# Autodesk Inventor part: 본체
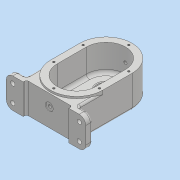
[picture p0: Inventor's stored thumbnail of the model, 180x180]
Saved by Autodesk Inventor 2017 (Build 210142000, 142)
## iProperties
Part Number: 본체
Material: 일반
Document SubType Name: Modeling
Designer: MRC
Density: 1 g/cm^3
Appearance: 기본값
Author: MRC
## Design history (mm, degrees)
sketch "스케치1"
  geometry: L1 (0, 0)-(0, -45); L2 (-40, 0)-(-40, -45); L3 (40, -45)-(40, 0); A1 r 40 centre (0, 0) between (40, 0) and (-40, 0); A2 r 40 centre (0, -45) between (-40, -45) and (40, -45); 1 further point
  constraints: 8 end point, 4 point on circle, 4 tangent, 2 centre point, 1 midpoint, 1 parallel, 1 vertical
  dimensions: "d0" = 45 distance of L1.start L1.end; "d1" = 80 diameter of A2
extrude "돌출1" new body sketch "스케치1" distance "d2" = 21; taper "d4" = 0 deg; dims "d3" = 28, "d5" = 0
sketch "스케치2"
  geometry: L1 (0, 0)-(0, -45); L2 (-30, 0)-(-30, -45); L3 (30, -45)-(30, 0); A1 r 40 centre (0, -45) between (-40, -45) and (40, -45) reference; A2 r 40 centre (0, 0) between (40, 0) and (-40, 0) reference; A3 r 30 centre (0, 0) between (30, 0) and (-30, 0); A4 r 30 centre (0, -45) between (-30, -45) and (30, -45); 1 further point
  constraints: 8 end point, 4 point on circle, 4 tangent, 2 centre point, 1 midpoint, 1 parallel, 1 vertical
  dimensions: "d6" = 30 radius of A3
extrude "돌출2" cut sketch "스케치2" distance "d7" = 41; taper "d8" = 0 deg
sketch "스케치3"
  geometry: L1 (0, 0)-(0, -45); L2 (-26, 0)-(-26, -45); L3 (26, -45)-(26, 0); A1 r 40 centre (0, 0) between (40, 0) and (-40, 0) reference; A2 r 40 centre (0, -45) between (-40, -45) and (40, -45) reference; A3 r 26 centre (0, 0) between (26, 0) and (-26, 0); A4 r 26 centre (0, -45) between (-26, -45) and (26, -45); 1 further point
  constraints: 8 end point, 4 point on circle, 4 tangent, 2 centre point, 1 midpoint, 1 parallel, 1 vertical
  dimensions: "d9" = 52 diameter of A4
extrude "돌출3" join sketch "스케치3" distance "d10" = 11; taper "d11" = 0 deg
sketch "스케치4"
  geometry: L1 (-26, 0)-(-26, -45) reference; L2 (26, -45)-(26, 0) reference; L3 (-26, -30)-(26, -30); A1 r 26 centre (0, 0) between (26, 0) and (-26, 0) reference
  constraints: 2 end point, 2 point on line, 1 perpendicular
  dimensions: "d12" = 30 distance from line of A1.centre L3
extrude "돌출4" cut sketch "스케치4" distance "d13" = 3; taper "d14" = 0 deg
hole "구멍1" diameter "d17" = 22; stored, may be unused: countersink angle "d21" = 90 deg, drill point angle "d23" = 118 deg; dims "d15" = 10, "d16" = 10, "d18" = 6, "d19" = 28, "d20" = 8, "d22" = 8
sketch "스케치5"
  geometry: C1 r 11 at (0, 0) reference; C2 r 14 at (0, 0); A1 r 26 centre (0, 0) between (26, 0) and (-26, 0) reference
  constraints: 1 centre point, 1 coincident
  dimensions: "d24" = 28 diameter of C2
extrude "돌출5" cut sketch "스케치5" distance "d25" = 4; taper "d26" = 0 deg
hole "구멍2" diameter "d32" = 20; stored, may be unused: countersink angle "d36" = 90 deg, drill point angle "d38" = 0 deg; dims "d30" = 10, "d31" = 10, "d33" = 6, "d34" = 28, "d35" = 8, "d37" = 12
fillet "모깎기1" dims "d39" = 3
fillet "모깎기2" dims "d40" = 0.3
chamfer "모따기2" distance "d41" = 1; stored, may be unused: second distance "d42" = 2, angle "d43" = 45 deg
sketch "스케치6"
  geometry: L1 (-40, 0)-(-40, -45) reference; L2 (-40, -45)-(-40, -82); L3 (-40, -82)-(-61, -82); L4 (-61, -82)-(-61, -92); L5 (-61, -92)-(61, -92); L6 (61, -92)-(61, -82); L7 (61, -82)-(40, -82); L8 (-40, -82)-(-40, -45); L9 (40, -45)-(40, -82); A1 r 26 centre (0, 0) between (26, 0) and (-26, 0) reference; A2 r 40 centre (0, -45) between (-40, -45) and (40, -45) reference; A3 r 40 centre (0, -45) between (-40, -45) and (40, -45) reference; 1 further point
  constraints: 16 end point, 5 perpendicular, 5 tangent, 3 point on line, 1 collinear, 1 midpoint, 1 vertical, 1 vertical alignment
  dimensions: "d44" = 10 distance of L5.end L6.end; "d45" = 92 distance from line of L5 A1.centre; "d46" = 122 distance of L4.end L5.end
extrude "돌출6" join sketch "스케치6" distance "d47" = 46; taper "d48" = 0 deg
sketch "스케치7"
  geometry: L1 (-61, -92)-(61, -92) reference; L2 (-35, -87)-(35, -87); L3 (35, -87)-(35, -92); L4 (35, -92)-(-35, -92); L5 (-35, -92)-(-35, -87); 1 further point
  constraints: 8 end point, 2 midpoint, 2 parallel, 1 horizontal, 1 perpendicular
  dimensions: "d49" = 70 distance of L3.end L4.end; "d50" = 5 distance of L2.end L3.end
extrude "돌출7" cut sketch "스케치7" stored distance "d51" = 46; taper "d52" = 0 deg
sketch "스케치10"
  geometry: A1 r 26 centre (0, 0) between (26, 0) and (-26, 0) reference; 1 further point
  constraints: 1 vertical alignment
  dimensions: "d75" = 20 distance of A1.centre point (0, 20)
hole "구멍5" sketch "스케치10" at (0, 20) diameter "d76" = 3.242; stored, may be unused: countersink angle "d80" = 90 deg, drill point angle "d82" = 118 deg; dims "d77" = 8, "d78" = 28, "d79" = 8, "d81" = 10
fillet "모깎기3" dims "d86" = 10
sketch "스케치11"
  geometry: A1 r 10 centre (-11, 10) between (-21, 10) and (-11, 0) reference; A2 r 10 centre (-11, 36) between (-11, 46) and (-21, 36) reference; 3 further points
  constraints: 2 coincident
hole "구멍6" sketch "스케치11" at (-11, 36), (-11, 10) diameter "d87" = 6.6; stored, may be unused: countersink angle "d91" = 90 deg, drill point angle "d93" = 118 deg; dims "d88" = 8, "d89" = 11, "d90" = 2, "d92" = 10
fillet "모깎기4" dims "d94" = 3
node "작업 평면1"
sketch "스케치12"
  geometry: C1 r 6 at (35, 28); 1 further point
  constraints: 1 centre point, 1 coincident
  dimensions: "d96" = 12 diameter of C1
extrude "돌출8" join sketch "스케치12" stored distance "d97" = 46; taper "d98" = 0 deg
hole "구멍7" diameter "d101" = 4.917; stored, may be unused: countersink angle "d105" = 90 deg, drill point angle "d107" = 118 deg; dims "d99" = 10, "d100" = 10, "d102" = 12, "d103" = 11, "d104" = 2, "d106" = 17.1
sketch "스케치14"
  geometry: L1 (-51, -92)-(-35, -92) reference; L2 (-32, -87)-(32, -87) reference; 2 further points
  constraints: 1 midpoint, 1 vertical alignment, 1 other
  dimensions: "d126" = 12 distance from line of point (0, -80) L1
feature "엠보싱1" sketch "스케치14" dims "d0" = 45, "d1" = 80, "d127" = 0.5, "d128" = 0
fillet "모깎기5" dims "d129" = 3
fillet "모깎기6" dims "d130" = 5
sketch "스케치15"
  geometry: L1 (-40, 0)-(-40, -45) reference; L2 (40, -45)-(40, 0) reference; L3 (-35, 0)-(-35, -45); L4 (35, -45)-(35, 0); A1 r 30 centre (0, 0) between (30, 0) and (-30, 0) reference; A2 r 40 centre (0, -45) between (-40, -45) and (40, -45) reference; A3 r 40 centre (0, 0) between (40, 0) and (-40, 0) reference; A4 r 35 centre (0, -45) between (-35, -45) and (35, -45); A5 r 35 centre (0, 0) between (35, 0) and (-35, 0); 6 further points
  constraints: 6 point on circle, 4 coincident, 4 end point, 2 centre point, 3 other
  dimensions: "d131" = 5 radial gap between concentric circles of A5 A1
hole "구멍10" sketch "스케치15" at (0, 35), (-35, 0), (-35, -45), (0, -80), (35, -45), (35, 0) diameter "d132" = 3.242; stored, may be unused: countersink angle "d136" = 90 deg, drill point angle "d138" = 118 deg; dims "d133" = 8, "d134" = 4, "d135" = 2, "d137" = 10
sketch "스케치16"
  geometry: L1 (72, 49)-(-8, 49) reference; 2 further points
  constraints: 1 coincident
  dimensions: "d139" = 21 distance from line of point (32, 28) L1
hole "구멍11" sketch "스케치16" at (32, 28) diameter "d140" = 4.917; stored, may be unused: countersink angle "d144" = 90 deg, drill point angle "d146" = 118 deg; dims "d141" = 12, "d142" = 12, "d143" = 1, "d145" = 17.1
node "솔리드1"
pattern_circular "원형 패턴3" dims angle "d84" = 360 deg
mirror "미러1"
other parameters: "d95" = -135
